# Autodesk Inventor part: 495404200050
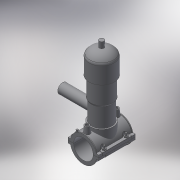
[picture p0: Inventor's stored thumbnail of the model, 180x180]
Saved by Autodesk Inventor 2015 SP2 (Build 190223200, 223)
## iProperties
Created: 2017-07
Part Number: 495404200050
Material: Generic
Description: PLASSON TAPPING VALVE 200-50
Document SubType Name: Modeling
Designer: KIM
Density: 1 g/cm^3
Appearance: Default
Author: KIM
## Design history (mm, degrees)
derived "495404-4954S4.ipt"
feature "Solid1::495404-4954S4.ipt"
feature "Solid2::495404-4954S4.ipt"
tag "TaggingFeature1"
body "Solid1"
body "Solid2"
other parameters: "d2" = 262.6, "d4" = 176, "d5" = 0, "d6" = 0.1, "d8" = 0, "d19" = 6, "d20" = 6, "d21" = 105.6, "d23" = 0, "d24" = 52.8, "d26" = 0, "d27" = 3, "d28" = 3, "d29" = 3, "d30" = 66.66667, "d31" = 6, "d32" = 0, "d33" = 0, "d34" = 0.6, "d40" = 121.68, "d47" = 168, "d70" = 15, "d72" = 0, "d73" = 6, "d75" = 5, "d76" = 0, "d79" = 15, "d80" = 70.4, "d82" = 5 deg, "d84" = 4, "d85" = 14, "d86" = 0, "d87" = 3, "d88" = 0, "d89" = 1, "d90" = 1, "d91" = 140.8, "d92" = 0, "d93" = 0.5, "d94" = 105.26316, "d96" = 241.02, "d97" = 3.52, "d98" = 0, "d120" = 140 deg, "d121" = 24.228, "d122" = 20 deg, "d123" = 468, "d124" = 140.4, "d126" = 0, "d143" = 206, "d145" = 26.15385, "d149" = 3, "d150" = 28.76923, "d153" = 176, "d154" = 0, "d156" = 117, "d157" = 160 deg, "d159" = 6.8, "d161" = 3, "d162" = 105.6, "d163" = 0, "d168" = 114.14634, "d170" = 3, "d172" = 0, "d173" = 1, "d176" = 20 deg, "d177" = 14, "d178" = 34, "d180" = 0, "d183" = 13.6, "d184" = 11.2, "d185" = 57.2, "d186" = 57.2, "d187" = 117, "d188" = 10.2, "d189" = 14, "d190" = 0, "d191" = 175.5, "d193" = 6.8, "d194" = 4.4, "d195" = 90 deg, "d197" = 0, "d199" = 0, "d205" = 14.64, "d206" = 81.33333, "d207" = 244, "d208" = 224.48, "d209" = 207.4, "d210" = 200.08, "d211" = 146.4, "d212" = 85.4, "d213" = 65.88, "d214" = 73.2, "d216" = 21.96, "d217" = 70.76, "d218" = 80.52, "d222" = 0, "d223" = 234, "d224" = 152, "d225" = 51, "d229" = 152, "d230" = 0, "B_" = 202, "H_" = 152, "L_" = 176, "d_t" = 6, "H_1" = 51, "H_2" = 244, "d148" = 3, "d160" = 3, "d169" = 3, "d192" = 6.8
